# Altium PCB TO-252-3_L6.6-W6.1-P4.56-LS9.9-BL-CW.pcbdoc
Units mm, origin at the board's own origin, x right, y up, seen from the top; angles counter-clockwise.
Board outline 19.55 x 24.27 mm, 2 copper layers (Top Layer, Bottom Layer), stack 0 mm thick; 1 components, 0 nets, 3 pads, 0 vias.
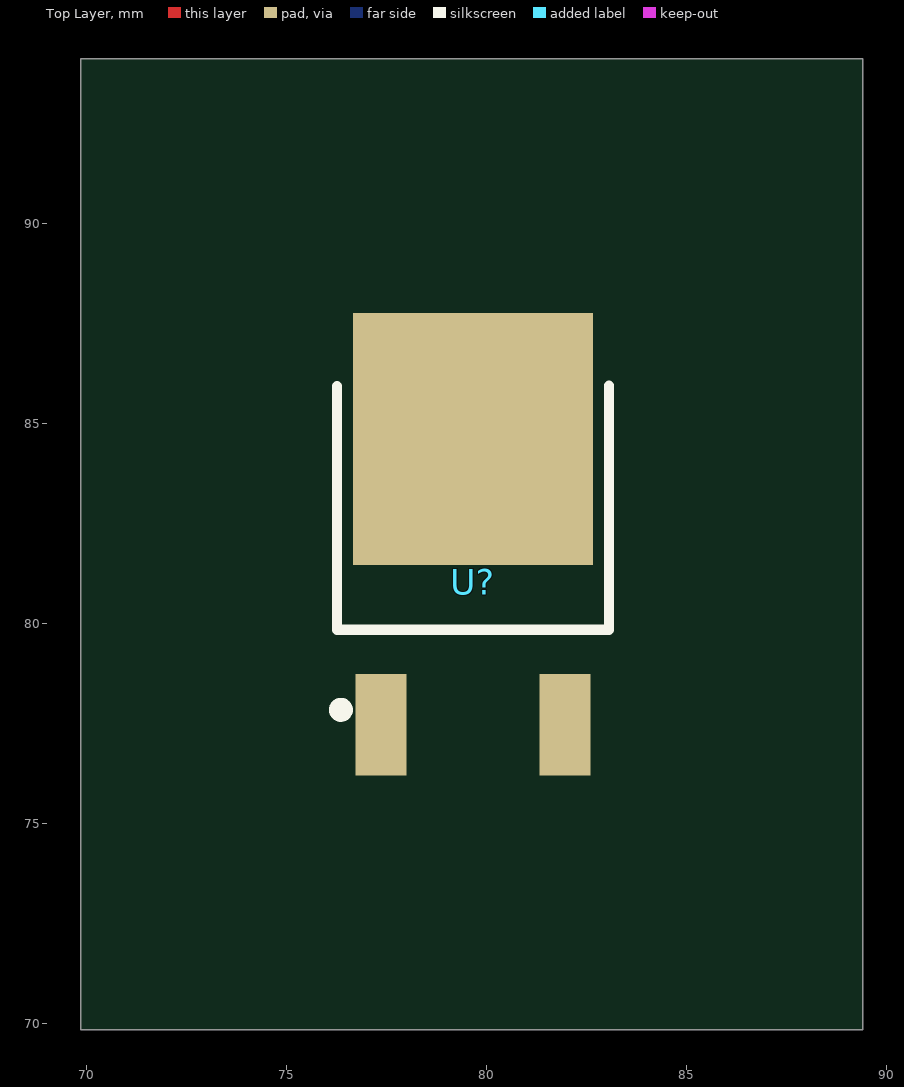
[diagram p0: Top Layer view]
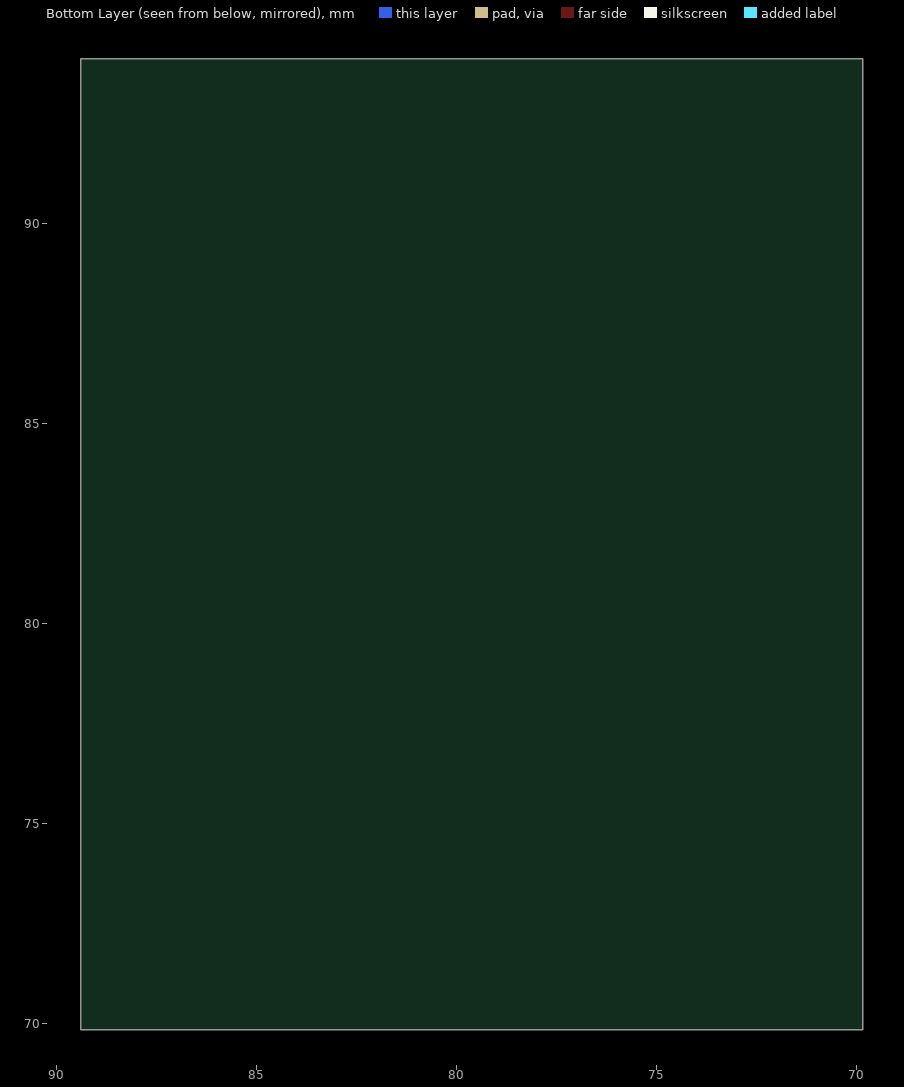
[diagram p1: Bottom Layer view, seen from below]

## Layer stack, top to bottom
Top Layer: signal copper (thickness not stored)
Bottom Layer: signal copper (thickness not stored)

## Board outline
89.4,69.85 69.85,69.85 69.85,94.117 89.4,94.117

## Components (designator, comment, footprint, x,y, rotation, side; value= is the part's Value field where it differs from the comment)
U? "" TO-252-3_L6.6-W6.1-P4.56-LS9.9-BL-CW 79.65,81.044 r0 top

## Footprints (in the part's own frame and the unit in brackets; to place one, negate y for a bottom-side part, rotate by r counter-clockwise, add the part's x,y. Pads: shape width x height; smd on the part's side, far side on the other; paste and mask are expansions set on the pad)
TO-252-3_L6.6-W6.1-P4.56-LS9.9-BL-CW [mm]
  rect 1.27x2.54 smd: 1(-2.3,-3.574) 3(2.3,-3.574)
  rect 6x6.3 smd: 2(-0.002,3.574)
  silkscreen extent -3.45,-3.35 3.4,4.9

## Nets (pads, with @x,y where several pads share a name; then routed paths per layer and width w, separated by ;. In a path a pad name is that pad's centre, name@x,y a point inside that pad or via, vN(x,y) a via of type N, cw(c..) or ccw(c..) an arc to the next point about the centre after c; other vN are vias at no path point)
pads on no net: U?.1 U?.2 U?.3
